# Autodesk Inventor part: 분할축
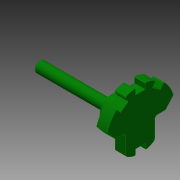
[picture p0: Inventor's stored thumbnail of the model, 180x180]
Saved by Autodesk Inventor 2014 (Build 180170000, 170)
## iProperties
Created: 2016-11
Part Number: 분할축
Material: 강철, 연강
Document SubType Name: Modeling
Designer: mduedu
Density: 1 g/cm^3
Appearance: 진녹색
Author: mduedu
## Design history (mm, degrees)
sketch "스케치1"
  geometry: C1 r 38 at (0, 0); 1 further point
  constraints: 1 centre point, 1 coincident
  dimensions: "d0" = 76 diameter of C1
extrude "돌출1" new body sketch "스케치1" distance "d1" = 12; taper "d2" = 0 deg
sketch "스케치2"
  geometry: L1 (0, 38)-(0, -38); L2 (5.5, 37.6)-(5.5, 31); L3 (5.5, 31)-(-5.5, 31); L4 (-5.5, 31)-(-5.5, 37.6); A1 r 38 centre (0, 0) between (0, 38) and (0, -38) reference; A2 r 38 centre (0, 0) between (5.5, 37.6) and (-5.5, 37.6); 2 further points
  constraints: 8 end point, 6 point on circle, 2 coincident, 2 vertical, 1 centre point, 1 horizontal, 1 midpoint, 1 parallel, 1 symmetric about line
  dimensions: "d3" = 11 distance of L2.end L3.end; "d5" = 31 distance from line of L3 point (0, 0)
extrude "돌출2" cut sketch "스케치2" stored distance "d7" = 12; taper "d8" = 0 deg
sketch "스케치3"
  geometry: L1 (-16, 0)-(-38, 0); L2 (16, 0)-(38, 0); L3 (0, -28)-(0, 28); L4 (-16, -22.978)-(-16, 0); L5 (16, -22.978)-(16, 0); A1 r 38 centre (0, 0) between (-5.5, 37.6) and (-17.061, 33.955) reference; A2 r 38 centre (0, 0) between (-38, 0) and (38, 0); A3 r 28 centre (0, 0) between (-16, -22.978) and (16, -22.978); 4 further points
  constraints: 10 end point, 7 point on circle, 3 coincident, 2 centre point, 2 horizontal alignment, 2 midpoint, 2 parallel, 1 collinear, 1 horizontal, 1 perpendicular, 1 other
  dimensions: "d13" = 32 distance between parallel lines of L5 L4; "d14" = 28 radius of A3
extrude "돌출3" cut sketch "스케치3" stored distance "d15" = 12; taper "d16" = 0 deg
sketch "스케치4"
  geometry: L1 (0, 0)-(0, -28); L2 (5.5, -27.455)-(5.5, -21); L3 (5.5, -21)-(-5.5, -21); L4 (-5.5, -21)-(-5.5, -27.455); A1 r 28 centre (0, 0) between (-16, -22.978) and (16, -22.978) reference; A2 r 28 centre (0, 0) between (16, -22.978) and (0, -28); A3 r 28 centre (0, 0) between (-5.5, -27.455) and (5.5, -27.455); 1 further point
  constraints: 8 end point, 7 point on circle, 2 centre point, 2 coincident, 1 horizontal, 1 parallel, 1 other
  dimensions: "d17" = 11 distance between parallel lines of L2 L4; "d19" = 21 distance from line of L3 point (0, 0)
extrude "돌출4" cut sketch "스케치4" stored distance "d20" = 12; taper "d21" = 0 deg
sketch "스케치5"
  geometry: C1 r 13 at (0, 0); 1 further point
  constraints: 1 centre point, 1 coincident
  dimensions: "d22" = 26 diameter of C1
extrude "돌출5" join sketch "스케치5" distance "d23" = 20; taper "d24" = 0 deg
sketch "스케치6"
  geometry: C1 r 6 at (0, 0); 1 further point
  constraints: 1 centre point, 1 coincident
  dimensions: "d25" = 12 diameter of C1
extrude "돌출6" join sketch "스케치6" distance "d26" = 80; taper "d27" = 0 deg
fillet "모깎기1" dims "d28" = 3
chamfer "모따기1" distance "d29" = 1; stored, may be unused: second distance "d30" = 2, angle "d31" = 45 deg
sketch "스케치7"
  geometry: L1 (-20, 13)-(-20, -13) reference; L2 (-20, 6)-(-99, 6) reference; L3 (0, 0)-(-20, 0); C1 r 1 at (-21, 6)
  constraints: 2 end point, 1 centre point, 1 midpoint, 1 tangent
  dimensions: "d32" = 2 diameter of C1; "d33" = 10 dimension on C1 L3
revolve "회전1" sketch "스케치7" stored, may be unused: angle "d34" = 90 deg
chamfer "모따기2" distance "d35" = 1; stored, may be unused: second distance "d36" = 2, angle "d37" = 45 deg
chamfer "모따기3" distance "d38" = 10; stored, may be unused: second distance "d39" = 2, angle "d40" = 45 deg
chamfer "모따기4" distance "d41" = 1; stored, may be unused: second distance "d42" = 2, angle "d43" = 45 deg
fillet "모깎기2" dims "d44" = 3
node "솔리드1"
pattern_circular "원형 패턴1" dims angle "d10" = 35 deg
other parameters: "d12" = 56
